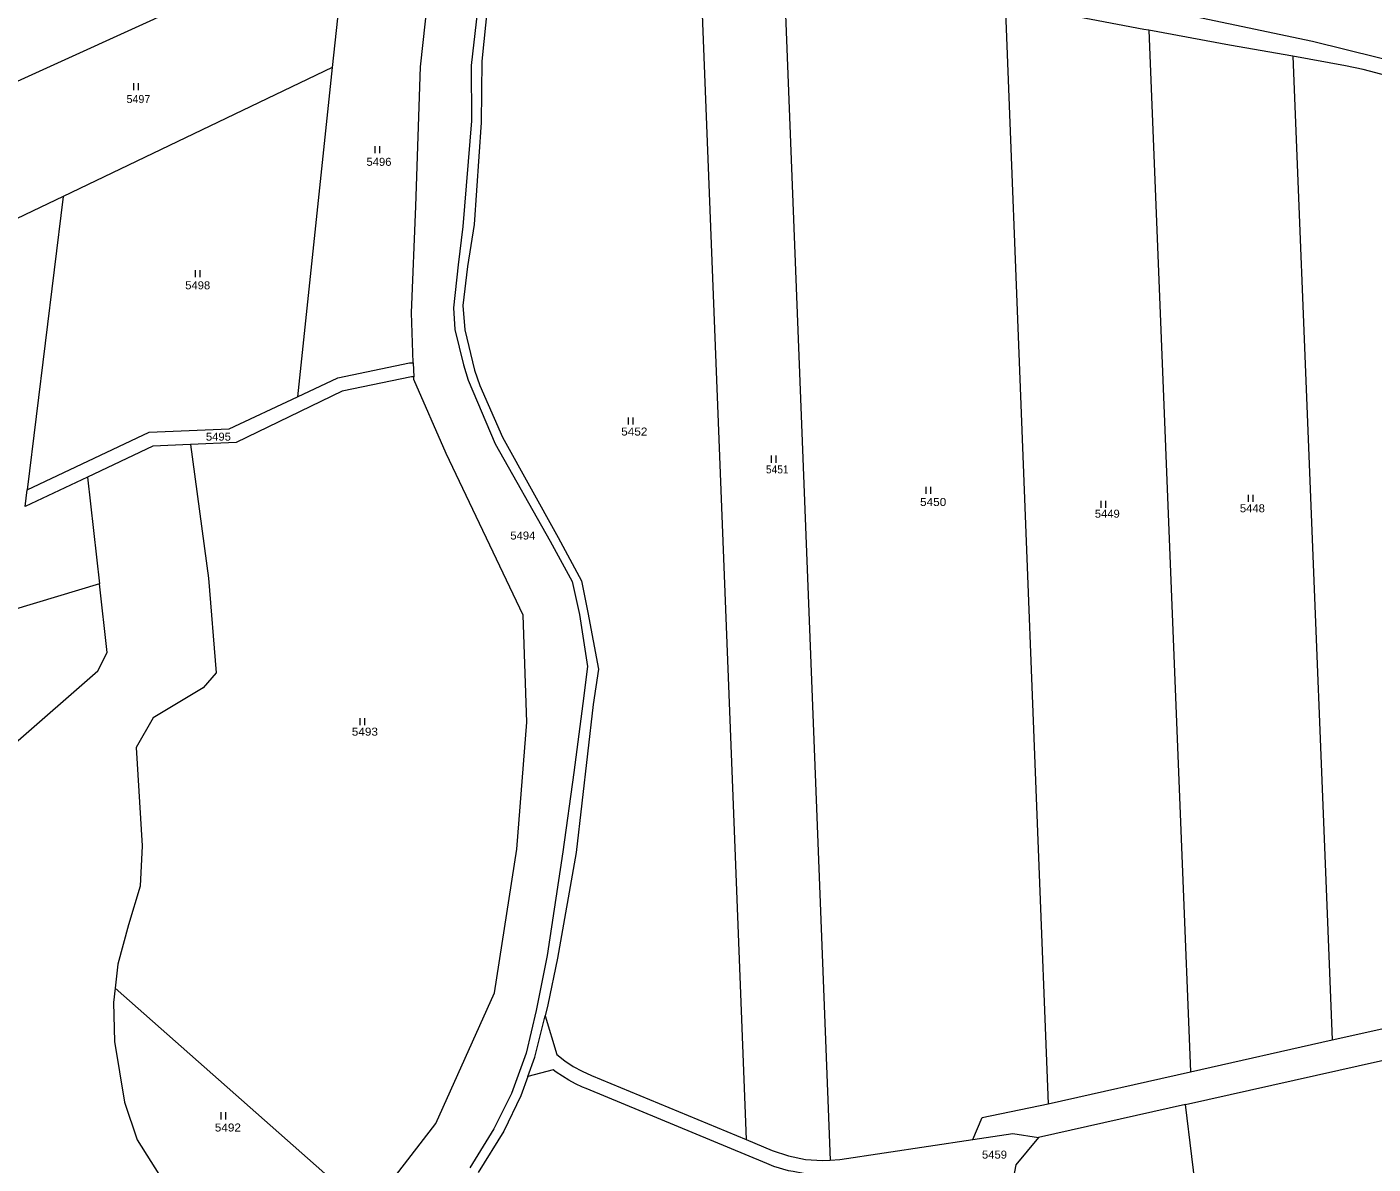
# Model space of a CAD drawing. Extents: x -590528 to -586543, y -1119609 to -1116685.
# Drawn here: x -589321.5 to -589035.6, y -1118965.6 to -1118724 of the extents above; entities that cross this region are included whole.
import ezdxf

# ---------------------------------------------------------------- set-up
doc = ezdxf.new("R2010")
doc.units = 0
doc.header["$LTSCALE"] = 0.68
for name, color, linetype, lineweight in [('1', 7, 'Continuous', 13), ('3', 7, 'Continuous', 13), ('6', 7, 'Continuous', 13)]:
    doc.layers.add(name, color=color, linetype=linetype, lineweight=lineweight)

msp = doc.modelspace()

# ---------------------------------------------------------------- linework, layer by layer
at = {"layer": '1'}
for p, q in [((-589178.74, -1118705.81), (-589171.69, -1118885.67)), ((-589160.9, -1118709.58), (-589153.9, -1118888.22)), ((-589113.78, -1118718.99), (-589106.81, -1118896.9)), ((-589083.26, -1118724.75), (-589076.17, -1118901.8)), ((-589052.64, -1118730.29), (-589045.44, -1118910.67)), ((-589256.7, -1118732.69), (-589264.1, -1118802.62)), ((-589313.85, -1118760.05), (-589321.52, -1118822.4)), ((-589239.49, -1118795.41), (-589239.38, -1118798.4)), ((-589264.1, -1118802.62), (-589255.51, -1118798.57)), ((-589171.69, -1118885.67), (-589168.76, -1118960.42)), ((-589153.9, -1118888.22), (-589150.9, -1118964.78)), ((-589106.81, -1118896.9), (-589104.62, -1118952.8)), ((-589076.17, -1118901.8), (-589074.4, -1118946)), ((-589045.44, -1118910.67), (-589044.3, -1118939.23)), ((-589075.45, -1118952.93), (-588900.71, -1118913.73)), ((-589044.3, -1118939.23), (-589013.02, -1118932.18)), ((-589074.4, -1118946), (-589044.3, -1118939.23)), ((-589203.6, -1118945.89), (-589201.64, -1118946.8)), ((-589104.62, -1118952.8), (-589074.4, -1118946)), ((-589201.64, -1118946.8), (-589168.76, -1118960.42)), ((-589150.9, -1118964.78), (-589148.89, -1118964.66))]:
    msp.add_line(p, q, dxfattribs=at)
for points in [[(-589223.74, -1118691.09), (-589223.64, -1118701.8), (-589224.28, -1118706.21), (-589226.14, -1118722.99), (-589227.15, -1118732.22), (-589227.12, -1118744), (-589228.96, -1118766.41), (-589229.92, -1118774.59), (-589230.97, -1118783.69), (-589230.65, -1118788.32)], [(-589138.64, -1118714.32), (-589160.9, -1118709.58), (-589178.74, -1118705.81), (-589183.07, -1118704.74), (-589217.13, -1118696.31), (-589221.87, -1118694.7), (-589222.01, -1118701.14), (-589222.27, -1118706.68), (-589223.73, -1118719.52), (-589224.93, -1118731.32), (-589225.04, -1118744.37), (-589226.52, -1118766.05), (-589227.99, -1118774.92), (-589228.98, -1118783.2), (-589228.54, -1118788.4)], [(-589239.88, -1118784.8), (-589238.92, -1118762.12), (-589237.96, -1118732.52), (-589234.36, -1118699.45), (-589254.18, -1118708.99), (-589256.7, -1118732.69)], [(-589256.7, -1118732.69), (-589313.85, -1118760.05), (-589348.37, -1118776.57), (-589341.68, -1118743.8), (-589294.6, -1118722.4), (-589254.18, -1118703.14)], [(-589145.07, -1118707.01), (-589112.04, -1118714.14), (-589093.46, -1118717.9), (-589084.16, -1118719.58), (-589048.51, -1118727.05), (-589020.73, -1118733.92)], [(-589014.27, -1118739.7), (-589020.72, -1118737.84), (-589032.65, -1118734.43), (-589037.74, -1118733.12), (-589041.46, -1118732.29), (-589052.64, -1118730.29), (-589066.14, -1118727.92), (-589083.26, -1118724.75), (-589084.27, -1118724.57), (-589113.78, -1118718.99), (-589138.64, -1118714.32)], [(-589255.51, -1118798.57), (-589240.25, -1118795.4), (-589239.49, -1118795.41), (-589239.88, -1118784.8)], [(-589230.65, -1118788.32), (-589228.82, -1118795.85), (-589227.8, -1118799.11), (-589222.08, -1118812.62), (-589210.43, -1118833.31), (-589205.71, -1118841.87), (-589204.2, -1118848.85), (-589202.45, -1118859.89), (-589203.48, -1118867.78), (-589205.41, -1118882.45)], [(-589228.54, -1118788.4), (-589226.5, -1118796.98), (-589225.35, -1118800.22), (-589220.56, -1118811.19), (-589208.73, -1118832.53), (-589203.76, -1118841.69), (-589202.38, -1118848.47), (-589200.14, -1118860.5), (-589201.29, -1118867.99)], [(-589215.33, -1118871.7), (-589216.15, -1118849), (-589232.47, -1118814.64), (-589239.36, -1118798.96), (-589239.38, -1118798.4), (-589239.85, -1118798.4), (-589254.55, -1118801.44)], [(-589308.68, -1118819.69), (-589321.93, -1118825.91), (-589321.52, -1118822.4), (-589295.55, -1118810.14), (-589278.56, -1118809.42), (-589264.1, -1118802.62)], [(-589254.55, -1118801.44), (-589277.07, -1118812.36), (-589286.77, -1118812.77), (-589282.98, -1118841.17), (-589281.35, -1118861.24), (-589284.1, -1118864.42), (-589294.74, -1118870.78), (-589298.33, -1118877.13)], [(-589286.77, -1118812.77), (-589294.82, -1118813.11), (-589308.68, -1118819.69), (-589306.14, -1118842.33)], [(-589342.68, -1118892.44), (-589306.51, -1118860.81), (-589304.51, -1118856.92), (-589306.14, -1118842.33), (-589407.16, -1118872.82)], [(-589201.29, -1118867.99), (-589204.86, -1118899.43), (-589208.82, -1118921.88)], [(-589222.22, -1118929.2), (-589217.46, -1118898.69), (-589215.33, -1118871.7)], [(-589298.33, -1118877.13), (-589297.08, -1118898), (-589297.52, -1118906.57), (-589299.99, -1118914.82), (-589302.26, -1118923.13), (-589302.81, -1118928.26)], [(-589205.41, -1118882.45), (-589207.68, -1118899.28), (-589211.07, -1118921.29)], [(-589211.07, -1118921.29), (-589213.41, -1118933.02), (-589215.51, -1118942.06), (-589218.62, -1118950.61), (-589222.35, -1118958.09), (-589227.44, -1118966.4)], [(-589208.82, -1118921.88), (-589210.9, -1118931.8), (-589211.49, -1118934.15), (-589209, -1118942.35), (-589207.29, -1118943.66), (-589205.49, -1118944.85), (-589203.6, -1118945.89)], [(-589244.28, -1118979.99), (-589302.81, -1118928.26), (-589303.13, -1118931.27), (-589302.96, -1118939.56), (-589300.81, -1118952.46), (-589298.16, -1118960.47), (-589289.4, -1118974.28), (-589278.92, -1118971.37), (-589273.48, -1118972.5), (-589271.08, -1118977.59), (-589269.63, -1118995.64), (-589268.78, -1119004.49), (-589264.32, -1119011.36), (-589262.78, -1119015.15), (-589262.05, -1119019.9), (-589260.68, -1119011.59)], [(-589245.88, -1118971.48), (-589234.66, -1118956.99), (-589222.22, -1118929.2)], [(-589215.15, -1118947), (-589213.69, -1118942.87), (-589211.49, -1118934.15)], [(-589202.79, -1118949.57), (-589203.54, -1118949.26), (-589204.99, -1118948.57), (-589206.41, -1118947.8), (-589207.79, -1118946.96), (-589209.12, -1118946.06), (-589209.76, -1118945.57), (-589215.15, -1118947), (-589216.61, -1118951.13), (-589220.28, -1118958.65), (-589225.67, -1118967.41)], [(-589153.37, -1118967.89), (-589156.61, -1118967.62), (-589158.77, -1118967.21), (-589159.79, -1118967.02), (-589162.9, -1118966.09), (-589164.4, -1118965.47), (-589202.79, -1118949.57)], [(-589148.89, -1118964.66), (-589120.63, -1118960.39), (-589118.65, -1118955.73), (-589104.62, -1118952.8)], [(-589067.41, -1119019.21), (-589075.45, -1118952.93), (-589106.71, -1118959.94), (-589111.48, -1118965.77), (-589124.01, -1119031.91)], [(-589168.76, -1118960.42), (-589163.25, -1118962.7), (-589159.78, -1118963.88), (-589156.2, -1118964.61), (-589152.54, -1118964.87), (-589150.9, -1118964.78)], [(-589120.63, -1118960.39), (-589112.15, -1118959.11), (-589106.71, -1118959.94)]]:
    msp.add_lwpolyline(points, dxfattribs=at)
at = {"layer": '6'}
for p, q in [((-589298.83, -1118737.46), (-589298.83, -1118735.96)), ((-589297.83, -1118737.46), (-589297.83, -1118735.96)), ((-589247.59, -1118750.87), (-589247.59, -1118749.37)), ((-589246.59, -1118750.87), (-589246.59, -1118749.37)), ((-589285.75, -1118777.22), (-589285.75, -1118775.72)), ((-589284.75, -1118777.22), (-589284.75, -1118775.72)), ((-589193.74, -1118808.48), (-589193.74, -1118806.98)), ((-589192.74, -1118808.48), (-589192.74, -1118806.98)), ((-589163.37, -1118816.61), (-589163.37, -1118815.11)), ((-589162.37, -1118816.61), (-589162.37, -1118815.11)), ((-589130.53, -1118823.25), (-589130.53, -1118821.75)), ((-589129.53, -1118823.25), (-589129.53, -1118821.75)), ((-589062.08, -1118824.92), (-589062.08, -1118823.42)), ((-589061.08, -1118824.92), (-589061.08, -1118823.42)), ((-589093.4, -1118826.24), (-589093.4, -1118824.74)), ((-589092.4, -1118826.24), (-589092.4, -1118824.74)), ((-589250.74, -1118872.4), (-589250.74, -1118870.9)), ((-589249.74, -1118872.4), (-589249.74, -1118870.9)), ((-589280.28, -1118956.11), (-589280.28, -1118954.61)), ((-589279.28, -1118956.11), (-589279.28, -1118954.61))]:
    msp.add_line(p, q, dxfattribs=at)

# ---------------------------------------------------------------- texts
at = {"layer": '3'}
msp.add_text('5497', height=1.7, dxfattribs=at).set_placement((-589300.393, -1118740.22))
for s, width, p in [('5496', 1.05, (-589249.423, -1118753.55)), ('5498', 1.05, (-589287.923, -1118779.78)), ('5452', 1.1, (-589195.313, -1118810.85)), ('5495', 1.05, (-589283.523, -1118811.93)), ('5451', 0.95, (-589164.563, -1118818.89)), ('5450', 1.1, (-589131.833, -1118825.81)), ('5448', 1.05, (-589063.903, -1118827.15)), ('5449', 1.05, (-589094.723, -1118828.3)), ('5494', 1.05, (-589218.863, -1118832.94)), ('5493', 1.1, (-589252.543, -1118874.6)), ('5492', 1.1, (-589281.643, -1118958.69)), ('5459', 1.05, (-589118.683, -1118964.45))]:
    msp.add_text(s, height=1.7, dxfattribs=dict(at, width=width)).set_placement(p)

doc.saveas('drawing.dxf')
